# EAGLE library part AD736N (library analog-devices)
ANALOG DEVICES
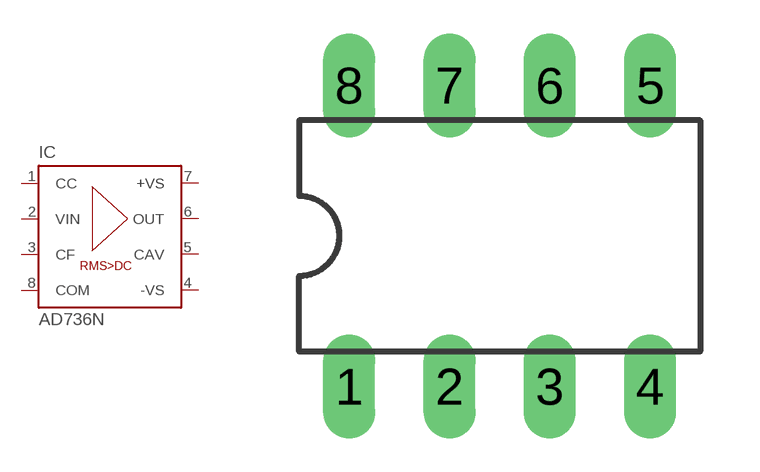
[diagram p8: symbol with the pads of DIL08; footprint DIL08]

Designator prefix IC

## AD736N (MF: ALTERA CORPORATION; MPN: AD736JN; OC_FARNELL: 9605061; OC_NEWARK: 05F7334)  [DIL08]
1  CC  pas
2  VIN  in
3  CF  pas
4  -VS  pwr
5  CAV  out
6  OUT  out
7  +VS  pwr
8  COM  pwr

## Footprint DIL08 (pad centres in mm)
Dual In Line Package
drill 0.813 long: 1 -3.81,-3.81; 2 -1.27,-3.81; 3 1.27,-3.81; 4 3.81,-3.81; 5 3.81,3.81; 6 1.27,3.81; 7 -1.27,3.81; 8 -3.81,3.81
